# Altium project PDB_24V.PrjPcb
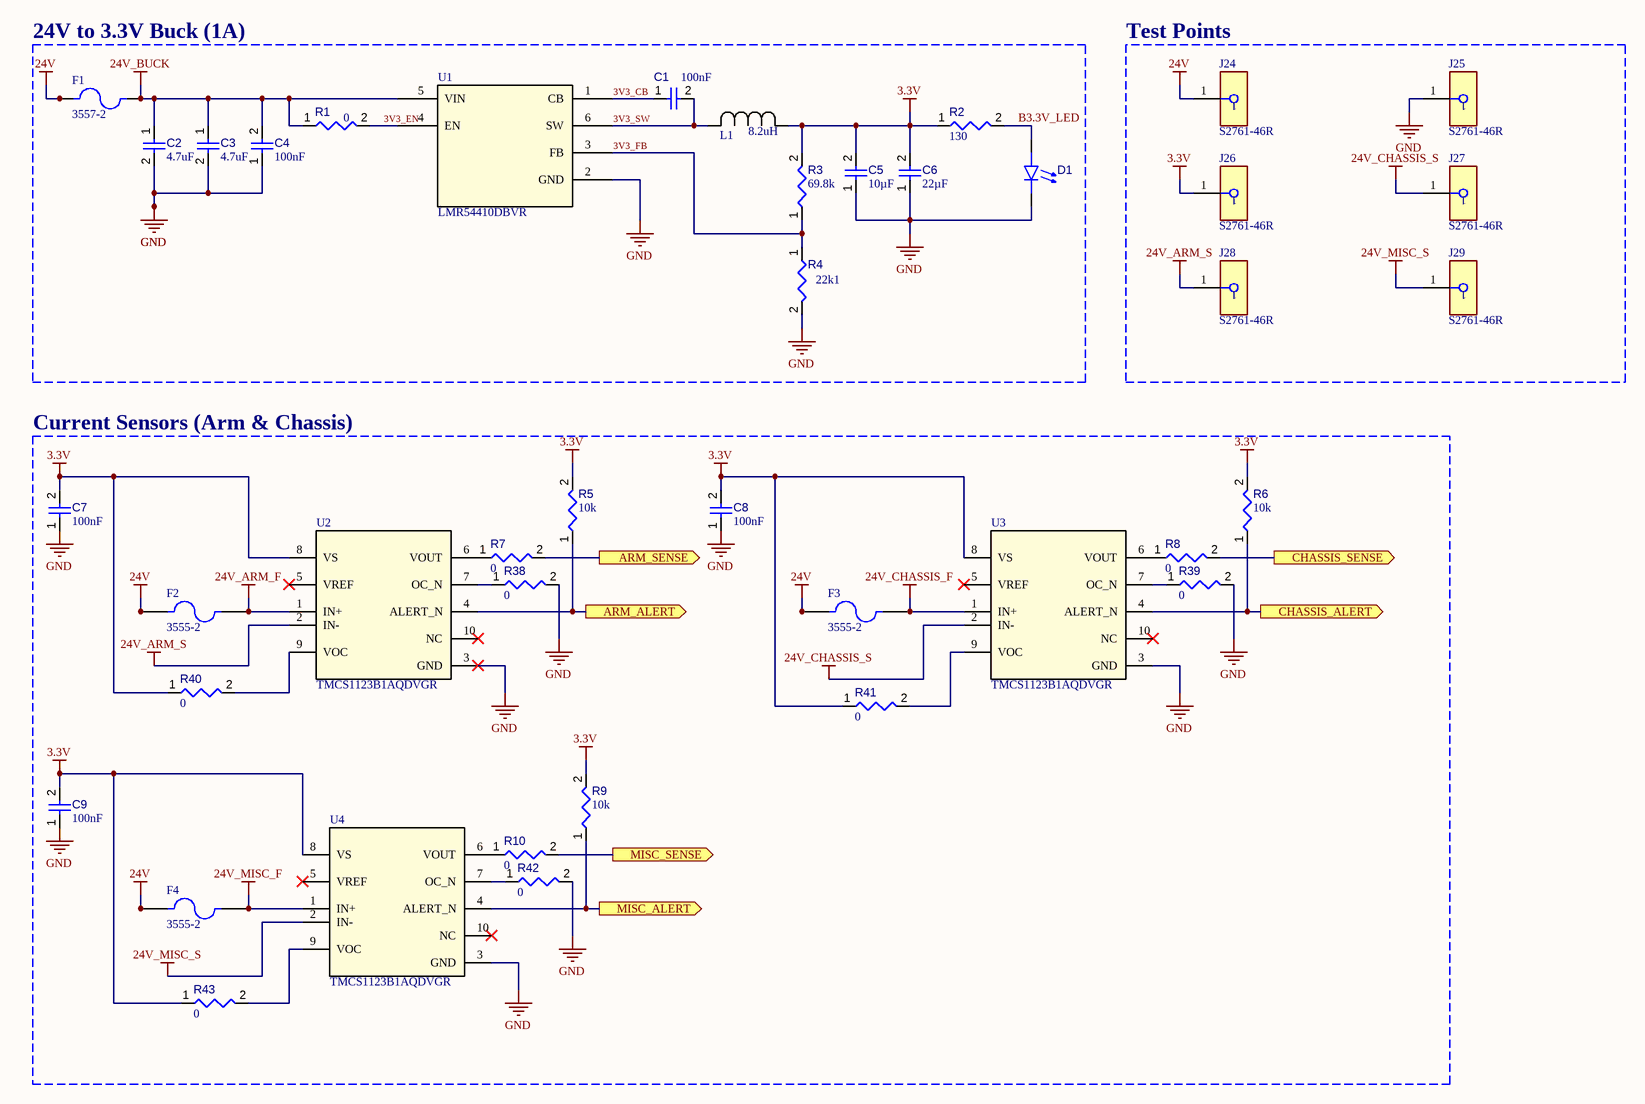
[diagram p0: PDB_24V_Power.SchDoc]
3 sheets, 170 parts. Net scope: flat (ports and power ports of the same name join across sheets).
Board file: PDB_24V.PcbDoc
Sheets:
  PDB_24V_Power.SchDoc
  PDB_24V_Connectors.SchDoc
  PDB_24V_MCU_Peripherals.SchDoc

## Sheet PDB_24V_Power.SchDoc
size A3

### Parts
C1  value 100nF  [FP-CGA3E-0_3-0_1-MFG]  (hidden comment: CGA3E3X8R1H104K080AB)
C2  value 4.7uF  [FP-1210-L_3_3_0_4-W_2_5_0-IPC_A]  (hidden comment: 12105C475KAT2A)
C3  value 4.7uF  [FP-1210-L_3_3_0_4-W_2_5_0-IPC_A]  (hidden comment: 12105C475KAT2A)
C4  value 100nF  [FP-CGA3E-0_3-0_1-MFG]  (hidden comment: CGA3E3X8R1H104K080AB)
C5  value 10µF  [TAYO-C1210-2_M]  (hidden comment: UMK325BJ106MM-T)
C6  value 22µF  [FP-GRM32-MFG]  (hidden comment: GRM32ER61E226KE15L)
C7  value 100nF  [FP-CL830-IPC_C]  (hidden comment: CL05B104KA5NNNC)
C8  value 100nF  [FP-CL830-IPC_C]  (hidden comment: CL05B104KA5NNNC)
C9  value 100nF  [FP-CL830-IPC_C]  (hidden comment: CL05B104KA5NNNC)
D1  150120VS75000  [WL-SMCW_1206_150120xx75000]  (value not drawn)
F1  3557-2  [FUSE_3557-2]
F2  3555-2  [FUSE_3555-2]
F3  3555-2  [FUSE_3555-2]
F4  3555-2  [FUSE_3555-2]
J24  S2761-46R  [FP-S2761-46R-MFG]
J25  S2761-46R  [FP-S2761-46R-MFG]
J26  S2761-46R  [FP-S2761-46R-MFG]
J27  S2761-46R  [FP-S2761-46R-MFG]
J28  S2761-46R  [FP-S2761-46R-MFG]
J29  S2761-46R  [FP-S2761-46R-MFG]
L1  value 8.2uH  [IND_BOURNS_SRN6045]  (hidden comment: SRN6045-8R2Y)
R1  value 0  [FP-RMCF0603-IPC_A]  (hidden comment: RMCF0603ZT0R00)
R2  value 130  [FP-AC0603-MFG]  (hidden comment: AC0603FR-07130RL)
R3  value 69.8k  [FP-CRCW0603-e3-MFG]  (hidden comment: CRCW060369K8FKEB)
R4  value 22k1  [FP-RMCF0603-MFG]  (hidden comment: RMCF0603FT22K1)
R5  value 10k  [FP-RC0603-0_55-MFG]  (hidden comment: RC0603FR-0710KL)
R6  value 10k  [FP-RC0603-0_55-MFG]  (hidden comment: RC0603FR-0710KL)
R7  value 0  [FP-RMCF0603-IPC_A]  (hidden comment: RMCF0603ZT0R00)
R8  value 0  [FP-RMCF0603-IPC_A]  (hidden comment: RMCF0603ZT0R00)
R9  value 10k  [FP-RC0603-0_55-MFG]  (hidden comment: RC0603FR-0710KL)
R10  value 0  [FP-RMCF0603-IPC_A]  (hidden comment: RMCF0603ZT0R00)
R38  value 0  [FP-RMCF0603-IPC_A]  (hidden comment: RMCF0603ZT0R00)
R39  value 0  [FP-RMCF0603-IPC_A]  (hidden comment: RMCF0603ZT0R00)
R40  value 0  [FP-RMCF0603-IPC_A]  (hidden comment: RMCF0603ZT0R00)
R41  value 0  [FP-RMCF0603-IPC_A]  (hidden comment: RMCF0603ZT0R00)
R42  value 0  [FP-RMCF0603-IPC_A]  (hidden comment: RMCF0603ZT0R00)
R43  value 0  [FP-RMCF0603-IPC_A]  (hidden comment: RMCF0603ZT0R00)
U1  LMR54410DBVR  [SOT-23-6-DBV_TEX]
U2  TMCS1123B1AQDVGR  [DVG0010A-MFG]
U3  TMCS1123B1AQDVGR  [DVG0010A-MFG]
U4  TMCS1123B1AQDVGR  [DVG0010A-MFG]

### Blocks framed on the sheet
24V to 3.3V Buck (1A): C1-C6 D1 F1 L1 R1-R4 U1
Test Points: J24-J29
Current Sensors (Arm & Chassis): C7-C9 F2-F4 R5-R10 R38-R43 U2-U4

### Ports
ARM_ALERT (out), ARM_SENSE (out), CHASSIS_ALERT (out), CHASSIS_SENSE (out), MISC_ALERT (out), MISC_SENSE (out)

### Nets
3.3V: C5.2 C6.2 C7.2 C8.2 C9.2 J26.1 L1.1 R2.1 R3.2 R5.2 R6.2 R9.2 R40.1 R41.1 R43.1 U2.8(VS) U3.8(VS) U4.8(VS)
24V: F1.1_1 F1.1_2 F2.1_1 F2.1_2 F3.1_1 F3.1_2 F4.1_1 F4.1_2 J24.1
24V_ARM_F: F2.2_1 F2.2_2 U2.1(IN+)
24V_ARM_S: J28.1 U2.2(IN-)
24V_BUCK: C2.1 C3.1 C4.2 F1.2_1 F1.2_2 R1.1 U1.5(VIN)
24V_CHASSIS_F: F3.2_1 F3.2_2 U3.1(IN+)
24V_CHASSIS_S: J27.1 U3.2(IN-)
24V_MISC_F: F4.2_1 F4.2_2 U4.1(IN+)
24V_MISC_S: J29.1 U4.2(IN-)
GND: C2.2 C3.2 C4.1 C5.1 C6.1 C7.1 C8.1 C9.1 D1.1(K) J25.1 R4.2 R38.2 R39.2 R42.2 U1.2(GND) U2.3(GND) U3.3(GND) U4.3(GND)
3V3_CB: C1.1 U1.1(CB)
3V3_EN: R1.2 U1.4(EN)
3V3_FB: R3.1 R4.1 U1.3(FB)
3V3_SW: C1.2 L1.2 U1.6(SW)
ARM_ALERT: R5.1 U2.4(ALERT_N) ; port ARM_ALERT
ARM_SENSE: R7.2 ; port ARM_SENSE
B3.3V_LED: D1.2(A) R2.2
CHASSIS_ALERT: R6.1 U3.4(ALERT_N) ; port CHASSIS_ALERT
CHASSIS_SENSE: R8.2 ; port CHASSIS_SENSE
MISC_ALERT: R9.1 U4.4(ALERT_N) ; port MISC_ALERT
MISC_SENSE: R10.2 ; port MISC_SENSE
NetR7_1: R7.1 U2.6(VOUT)
NetR8_1: R8.1 U3.6(VOUT)
NetR10_1: R10.1 U4.6(VOUT)
NetR38_1: R38.1 U2.7(OC_N)
NetR39_1: R39.1 U3.7(OC_N)
NetR40_2: R40.2 U2.9(VOC)
NetR41_2: R41.2 U3.9(VOC)
NetR42_1: R42.1 U4.7(OC_N)
NetR43_2: R43.2 U4.9(VOC)

Not connected (* = marked no-connect by the designer): U2 5(VREF)* 10(NC)*; U3 5(VREF)* 10(NC)*; U4 5(VREF)* 10(NC)*

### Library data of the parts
C1 C4 = CMP-001-00163-1: CGA Series 0603 0.1 uF 50 V ±10% Tolerance X8R Multilayer Ceramic Capacitor; Voltage Rating: 50V
C2 C3 = CMP-001-00137-1: Ceramic Capacitor, Multilayer, Ceramic, 50V, 10% +Tol, 10% -Tol, X7R, 15% TC, 4.7uF, Surface Mount, 1210
C5 = CMP-001-00183-1: 50V 10uF X5R ±20% 1210 Multilayer Ceramic Capacitors MLCC - SMD/SMT ROHS
C6 = CMP-001-00168-1: 25V 22uF X5R ±10% 1210 Multilayer Ceramic Capacitors MLCC - SMD/SMT ROHS
C7-C9 = CMP-001-00174-1: 25V 100nF X7R 卤10% 0402 Multilayer Ceramic Capacitors MLCC - SMD/SMT ROHS; Tolerance: 10%
D1 = CMP-007-00044-1: Single Color LED, Bright Green, Water Clear, 2mm; Forward Current: 30mA
F1 = CMP-005-00014-1: THM 2 in 1 Auto Blade Holder; MF: Keystone Electronics
F2-F4 = CMP-005-00015-2: Auto Fuse Holder, 1 Fuse, Blade, Standard, THM, 50Amp, Hi-Temp Nylon, UL94V-0; MF: Keystone Electronics
J24-J29 = CMP-002-00083-1: Interconnection Device
L1 = CMP-006-00036-1: Description; Manufacturer_Name: Bourns Electronics
R1 R7 R8 R10 R38-R43 = CMP-009-00236-1: Fixed Resistor, Metal Glaze/thick Film, 0.1W, 0ohm, Surface Mount, 0603; Power: 100mW
R2 = CMP-009-00292-1: Res Thick Film 0603 130 Ohm 1% 0.1W(1/10W) ±100ppm/C Pad SMD T/R Automotive AEC-Q200; Voltage Rating: 75V
R3 = CMP-009-00297-1: CRCW FIXED RESISTOR 0603 (1608Metric) Chip Resistor ±1% ±100ppm/C 69.8kOhm 0.1W 1/10W; Voltage Rating: 75V
R4 = CMP-009-00240-1: Fixed Resistor, Metal Glaze/thick Film, 0.1W, 22100ohm, 75V, 1% +/-Tol, 100ppm/Cel, Surface Mount, 0603; Power: 100mW
R5 R6 R9 = CMP-009-00288-1: 100mW Thick Film Resistors ±100ppm/℃ ±1% 10kΩ 0603 Chip Resistor - Surface Mount ROHS; Voltage Rating: 75V
U1 = CMP-00030-00008-3: 4V to 36V, 1A, 80-ÂµA Iq synchronous SIMPLE SWITCHERÂ® power converter 6-SOT-23 -40 to 125; Manufacturer_Name: Texas Instruments
U2-U4 = CMP-081-000000-2: Â±1300V reinforced isolation, 80ARMS 250kHz Hall-effect current sensor with AFR, reference and ALERT 10-SOIC -40 to 125; Manufacturer_Name: Texas Instruments

## Sheet PDB_24V_Connectors.SchDoc
size A3
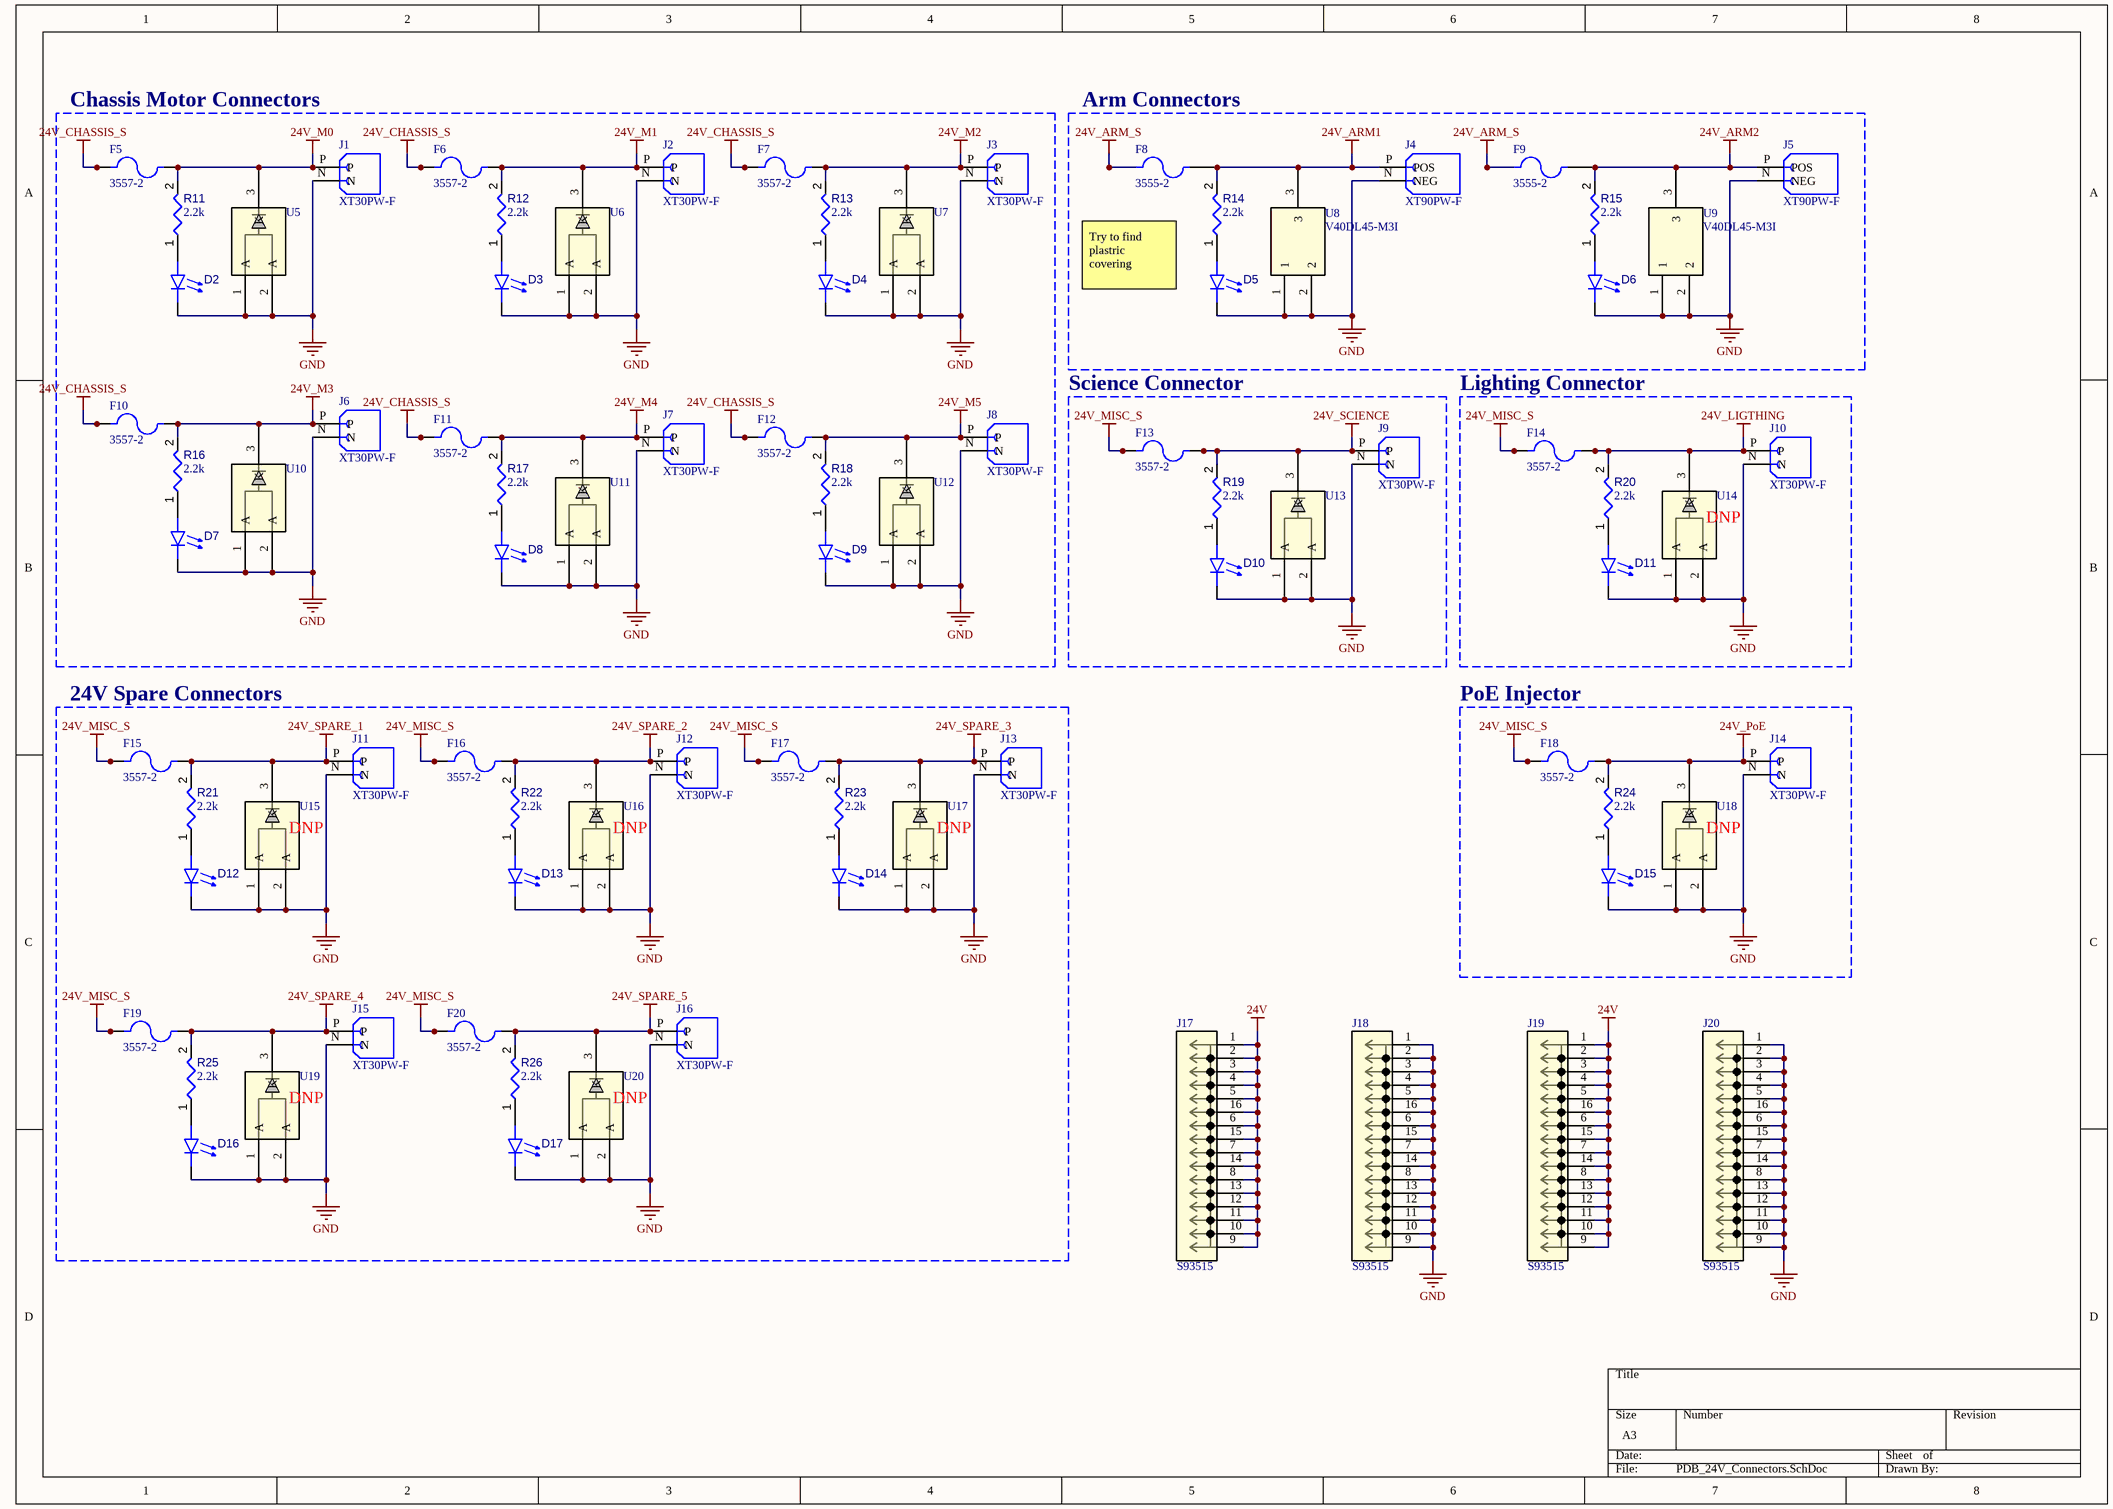
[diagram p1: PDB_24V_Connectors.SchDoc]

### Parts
D2  150120VS75000  [WL-SMCW_1206_150120xx75000]  (value not drawn)
D3  150120VS75000  [WL-SMCW_1206_150120xx75000]  (value not drawn)
D4  150120VS75000  [WL-SMCW_1206_150120xx75000]  (value not drawn)
D5  150120VS75000  [WL-SMCW_1206_150120xx75000]  (value not drawn)
D6  150120VS75000  [WL-SMCW_1206_150120xx75000]  (value not drawn)
D7  150120VS75000  [WL-SMCW_1206_150120xx75000]  (value not drawn)
D8  150120VS75000  [WL-SMCW_1206_150120xx75000]  (value not drawn)
D9  150120VS75000  [WL-SMCW_1206_150120xx75000]  (value not drawn)
D10  150120VS75000  [WL-SMCW_1206_150120xx75000]  (value not drawn)
D11  150120VS75000  [WL-SMCW_1206_150120xx75000]  (value not drawn)
D12  150120VS75000  [WL-SMCW_1206_150120xx75000]  (value not drawn)
D13  150120VS75000  [WL-SMCW_1206_150120xx75000]  (value not drawn)
D14  150120VS75000  [WL-SMCW_1206_150120xx75000]  (value not drawn)
D15  150120VS75000  [WL-SMCW_1206_150120xx75000]  (value not drawn)
D16  150120VS75000  [WL-SMCW_1206_150120xx75000]  (value not drawn)
D17  150120VS75000  [WL-SMCW_1206_150120xx75000]  (value not drawn)
F5  3557-2  [FUSE_3557-2]
F6  3557-2  [FUSE_3557-2]
F7  3557-2  [FUSE_3557-2]
F8  3555-2  [FUSE_3555-2]
F9  3555-2  [FUSE_3555-2]
F10  3557-2  [FUSE_3557-2]
F11  3557-2  [FUSE_3557-2]
F12  3557-2  [FUSE_3557-2]
F13  3557-2  [FUSE_3557-2]
F14  3557-2  [FUSE_3557-2]
F15  3557-2  [FUSE_3557-2]
F16  3557-2  [FUSE_3557-2]
F17  3557-2  [FUSE_3557-2]
F18  3557-2  [FUSE_3557-2]
F19  3557-2  [FUSE_3557-2]
F20  3557-2  [FUSE_3557-2]
J1  XT30PW-F  [AMASS_XT30PW-F]
J2  XT30PW-F  [AMASS_XT30PW-F]
J3  XT30PW-F  [AMASS_XT30PW-F]
J4  XT90PW-F  [AMASS_XT90PW-F]
J5  XT90PW-F  [AMASS_XT90PW-F]
J6  XT30PW-F  [AMASS_XT30PW-F]
J7  XT30PW-F  [AMASS_XT30PW-F]
J8  XT30PW-F  [AMASS_XT30PW-F]
J9  XT30PW-F  [AMASS_XT30PW-F]
J10  XT30PW-F  [AMASS_XT30PW-F]
J11  XT30PW-F  [AMASS_XT30PW-F]
J12  XT30PW-F  [AMASS_XT30PW-F]
J13  XT30PW-F  [AMASS_XT30PW-F]
J14  XT30PW-F  [AMASS_XT30PW-F]
J15  XT30PW-F  [AMASS_XT30PW-F]
J16  XT30PW-F  [AMASS_XT30PW-F]
J17  S93515  [CONN16_S93515_WRE]
J18  S93515  [CONN16_S93515_WRE]
J19  S93515  [CONN16_S93515_WRE]
J20  S93515  [CONN16_S93515_WRE]
R11  value 2.2k  [RESC1608X55X25LL10T15]  (hidden comment: RC0603FR-072K2L)
R12  value 2.2k  [RESC1608X55X25LL10T15]  (hidden comment: RC0603FR-072K2L)
R13  value 2.2k  [RESC1608X55X25LL10T15]  (hidden comment: RC0603FR-072K2L)
R14  value 2.2k  [RESC1608X55X25LL10T15]  (hidden comment: RC0603FR-072K2L)
R15  value 2.2k  [RESC1608X55X25LL10T15]  (hidden comment: RC0603FR-072K2L)
R16  value 2.2k  [RESC1608X55X25LL10T15]  (hidden comment: RC0603FR-072K2L)
R17  value 2.2k  [RESC1608X55X25LL10T15]  (hidden comment: RC0603FR-072K2L)
R18  value 2.2k  [RESC1608X55X25LL10T15]  (hidden comment: RC0603FR-072K2L)
R19  value 2.2k  [RESC1608X55X25LL10T15]  (hidden comment: RC0603FR-072K2L)
R20  value 2.2k  [RESC1608X55X25LL10T15]  (hidden comment: RC0603FR-072K2L)
R21  value 2.2k  [RESC1608X55X25LL10T15]  (hidden comment: RC0603FR-072K2L)
R22  value 2.2k  [RESC1608X55X25LL10T15]  (hidden comment: RC0603FR-072K2L)
R23  value 2.2k  [RESC1608X55X25LL10T15]  (hidden comment: RC0603FR-072K2L)
R24  value 2.2k  [RESC1608X55X25LL10T15]  (hidden comment: RC0603FR-072K2L)
R25  value 2.2k  [RESC1608X55X25LL10T15]  (hidden comment: RC0603FR-072K2L)
R26  value 2.2k  [RESC1608X55X25LL10T15]  (hidden comment: RC0603FR-072K2L)
U5  SDT30B100D1-13  [TO252_DIO]  (value not drawn)
U6  SDT30B100D1-13  [TO252_DIO]  (value not drawn)
U7  SDT30B100D1-13  [TO252_DIO]  (value not drawn)
U8  V40DL45-M3I  [SOT_45-M3I_VIS]
U9  V40DL45-M3I  [SOT_45-M3I_VIS]
U10  SDT30B100D1-13  [TO252_DIO]  (value not drawn)
U11  SDT30B100D1-13  [TO252_DIO]  (value not drawn)
U12  SDT30B100D1-13  [TO252_DIO]  (value not drawn)
U13  SDT30B100D1-13  [TO252_DIO]  (value not drawn)
U14  SDT30B100D1-13  [TO252_DIO]  (value not drawn)
U15  SDT30B100D1-13  [TO252_DIO]  (value not drawn)
U16  SDT30B100D1-13  [TO252_DIO]  (value not drawn)
U17  SDT30B100D1-13  [TO252_DIO]  (value not drawn)
U18  SDT30B100D1-13  [TO252_DIO]  (value not drawn)
U19  SDT30B100D1-13  [TO252_DIO]  (value not drawn)
U20  SDT30B100D1-13  [TO252_DIO]  (value not drawn)

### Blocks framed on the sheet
Chassis Motor Connectors: D2-D4 D7-D9 F5-F7 F10-F12 J1-J3 J6-J8 R11-R13 R16-R18 U5-U7 U10-U12
Arm Connectors: D5 D6 F8 F9 J4 J5 R14 R15 U8 U9
Science Connector: D10 F13 J9 R19 U13
Lighting Connector: D11 F14 J10 R20 U14
24V Spare Connectors: D12-D14 D16 D17 F15-F17 F19 F20 J11-J13 J15 J16 R21-R23 R25 R26 U15-U17 U19 U20
PoE Injector: D15 F18 J14 R24 U18

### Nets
24V: J17.1 J17.2 J17.3 J17.4 J17.5 J17.6 J17.7 J17.8 J17.9 J17.10 J17.11 J17.12 J17.13 J17.14 J17.15 J17.16 J19.1 J19.2 J19.3 J19.4 J19.5 J19.6 J19.7 J19.8 J19.9 J19.10 J19.11 J19.12 J19.13 J19.14 J19.15 J19.16
24V_ARM1: F8.2_1 F8.2_2 J4.P(POS) R14.2 U8.3
24V_ARM2: F9.2_1 F9.2_2 J5.P(POS) R15.2 U9.3
24V_ARM_S: F8.1_1 F8.1_2 F9.1_1 F9.1_2
24V_CHASSIS_S: F5.1_1 F5.1_2 F6.1_1 F6.1_2 F7.1_1 F7.1_2 F10.1_1 F10.1_2 F11.1_1 F11.1_2 F12.1_1 F12.1_2
24V_LIGTHING: F14.2_1 F14.2_2 J10.P R20.2 U14.3(K)
24V_M0: F5.2_1 F5.2_2 J1.P R11.2 U5.3(K)
24V_M1: F6.2_1 F6.2_2 J2.P R12.2 U6.3(K)
24V_M2: F7.2_1 F7.2_2 J3.P R13.2 U7.3(K)
24V_M3: F10.2_1 F10.2_2 J6.P R16.2 U10.3(K)
24V_M4: F11.2_1 F11.2_2 J7.P R17.2 U11.3(K)
24V_M5: F12.2_1 F12.2_2 J8.P R18.2 U12.3(K)
24V_MISC_S: F13.1_1 F13.1_2 F14.1_1 F14.1_2 F15.1_1 F15.1_2 F16.1_1 F16.1_2 F17.1_1 F17.1_2 F18.1_1 F18.1_2 F19.1_1 F19.1_2 F20.1_1 F20.1_2
24V_PoE: F18.2_1 F18.2_2 J14.P R24.2 U18.3(K)
24V_SCIENCE: F13.2_1 F13.2_2 J9.P R19.2 U13.3(K)
24V_SPARE_1: F15.2_1 F15.2_2 J11.P R21.2 U15.3(K)
24V_SPARE_2: F16.2_1 F16.2_2 J12.P R22.2 U16.3(K)
24V_SPARE_3: F17.2_1 F17.2_2 J13.P R23.2 U17.3(K)
24V_SPARE_4: F19.2_1 F19.2_2 J15.P R25.2 U19.3(K)
24V_SPARE_5: F20.2_1 F20.2_2 J16.P R26.2 U20.3(K)
GND: D2.1(K) D3.1(K) D4.1(K) D5.1(K) D6.1(K) D7.1(K) D8.1(K) D9.1(K) D10.1(K) D11.1(K) D12.1(K) D13.1(K) D14.1(K) D15.1(K) D16.1(K) D17.1(K) J1.N J2.N J3.N J4.N(NEG) J5.N(NEG) J6.N J7.N J8.N J9.N J10.N J11.N J12.N J13.N J14.N J15.N J16.N J18.1 J18.2 J18.3 J18.4 J18.5 J18.6 J18.7 J18.8 J18.9 J18.10 J18.11 J18.12 J18.13 J18.14 J18.15 J18.16 J20.1 J20.2 J20.3 J20.4 J20.5 J20.6 J20.7 J20.8 J20.9 J20.10 J20.11 J20.12 J20.13 J20.14 J20.15 J20.16 U5.1(A) U5.2(A) U6.1(A) U6.2(A) U7.1(A) U7.2(A) U8.1 U8.2 U9.1 U9.2 U10.1(A) U10.2(A) U11.1(A) U11.2(A) U12.1(A) U12.2(A) U13.1(A) U13.2(A) U14.1(A) U14.2(A) U15.1(A) U15.2(A) U16.1(A) U16.2(A) U17.1(A) U17.2(A) U18.1(A) U18.2(A) U19.1(A) U19.2(A) U20.1(A) U20.2(A)
NetD2_2: D2.2(A) R11.1
NetD3_2: D3.2(A) R12.1
NetD4_2: D4.2(A) R13.1
NetD5_2: D5.2(A) R14.1
NetD6_2: D6.2(A) R15.1
NetD7_2: D7.2(A) R16.1
NetD8_2: D8.2(A) R17.1
NetD9_2: D9.2(A) R18.1
NetD10_2: D10.2(A) R19.1
NetD11_2: D11.2(A) R20.1
NetD12_2: D12.2(A) R21.1
NetD13_2: D13.2(A) R22.1
NetD14_2: D14.2(A) R23.1
NetD15_2: D15.2(A) R24.1
NetD16_2: D16.2(A) R25.1
NetD17_2: D17.2(A) R26.1

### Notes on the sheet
- Try to find plastric covering
- (near U14) DNP
- (near U15) DNP
- (near U16) DNP
- (near U17) DNP
- (near U18) DNP
- (near U19) DNP
- (near U20) DNP

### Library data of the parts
D2-D17 = CMP-007-00044-1: as D1 on sheet PDB_24V_Power
F5-F7 F10-F20 = CMP-005-00014-1: as F1 on sheet PDB_24V_Power
F8 F9 = CMP-005-00015-2: as F2 on sheet PDB_24V_Power
J1-J3 J6-J16 = CMP-002-00091-1: Socket; DC supply; XT30; female; PIN: 2; on PCBs; THT; yellow; 15A; MF: amass
J4 J5 = CMP-002-00096-1: Socket, DC supply, XT90, female, PIN:2, on PCBs, THT; MF: AMASS
J17-J20 = CMP-083-000000-2: Description; Manufacturer_Name: Wurth Electronics
R11-R26 = CMP-009-00296-1: 100Mw Thick Film Resistors 100Ppm/ 1% 2.2K 0603 Chip Resistor Surface Mount Rohs; Voltage Rating: 75V
U5-U7 U10-U20 = CMP-004-00037-2: Description; Manufacturer_Name: Diodes Inc
U8 U9 = CMP-079-000001-3: 40A, 45V,TRENCH SKY RECT.; Manufacturer_Part_Number: V40DL45-M3/I; Manufacturer_Name: Vishay

## Sheet PDB_24V_MCU_Peripherals.SchDoc
size A3
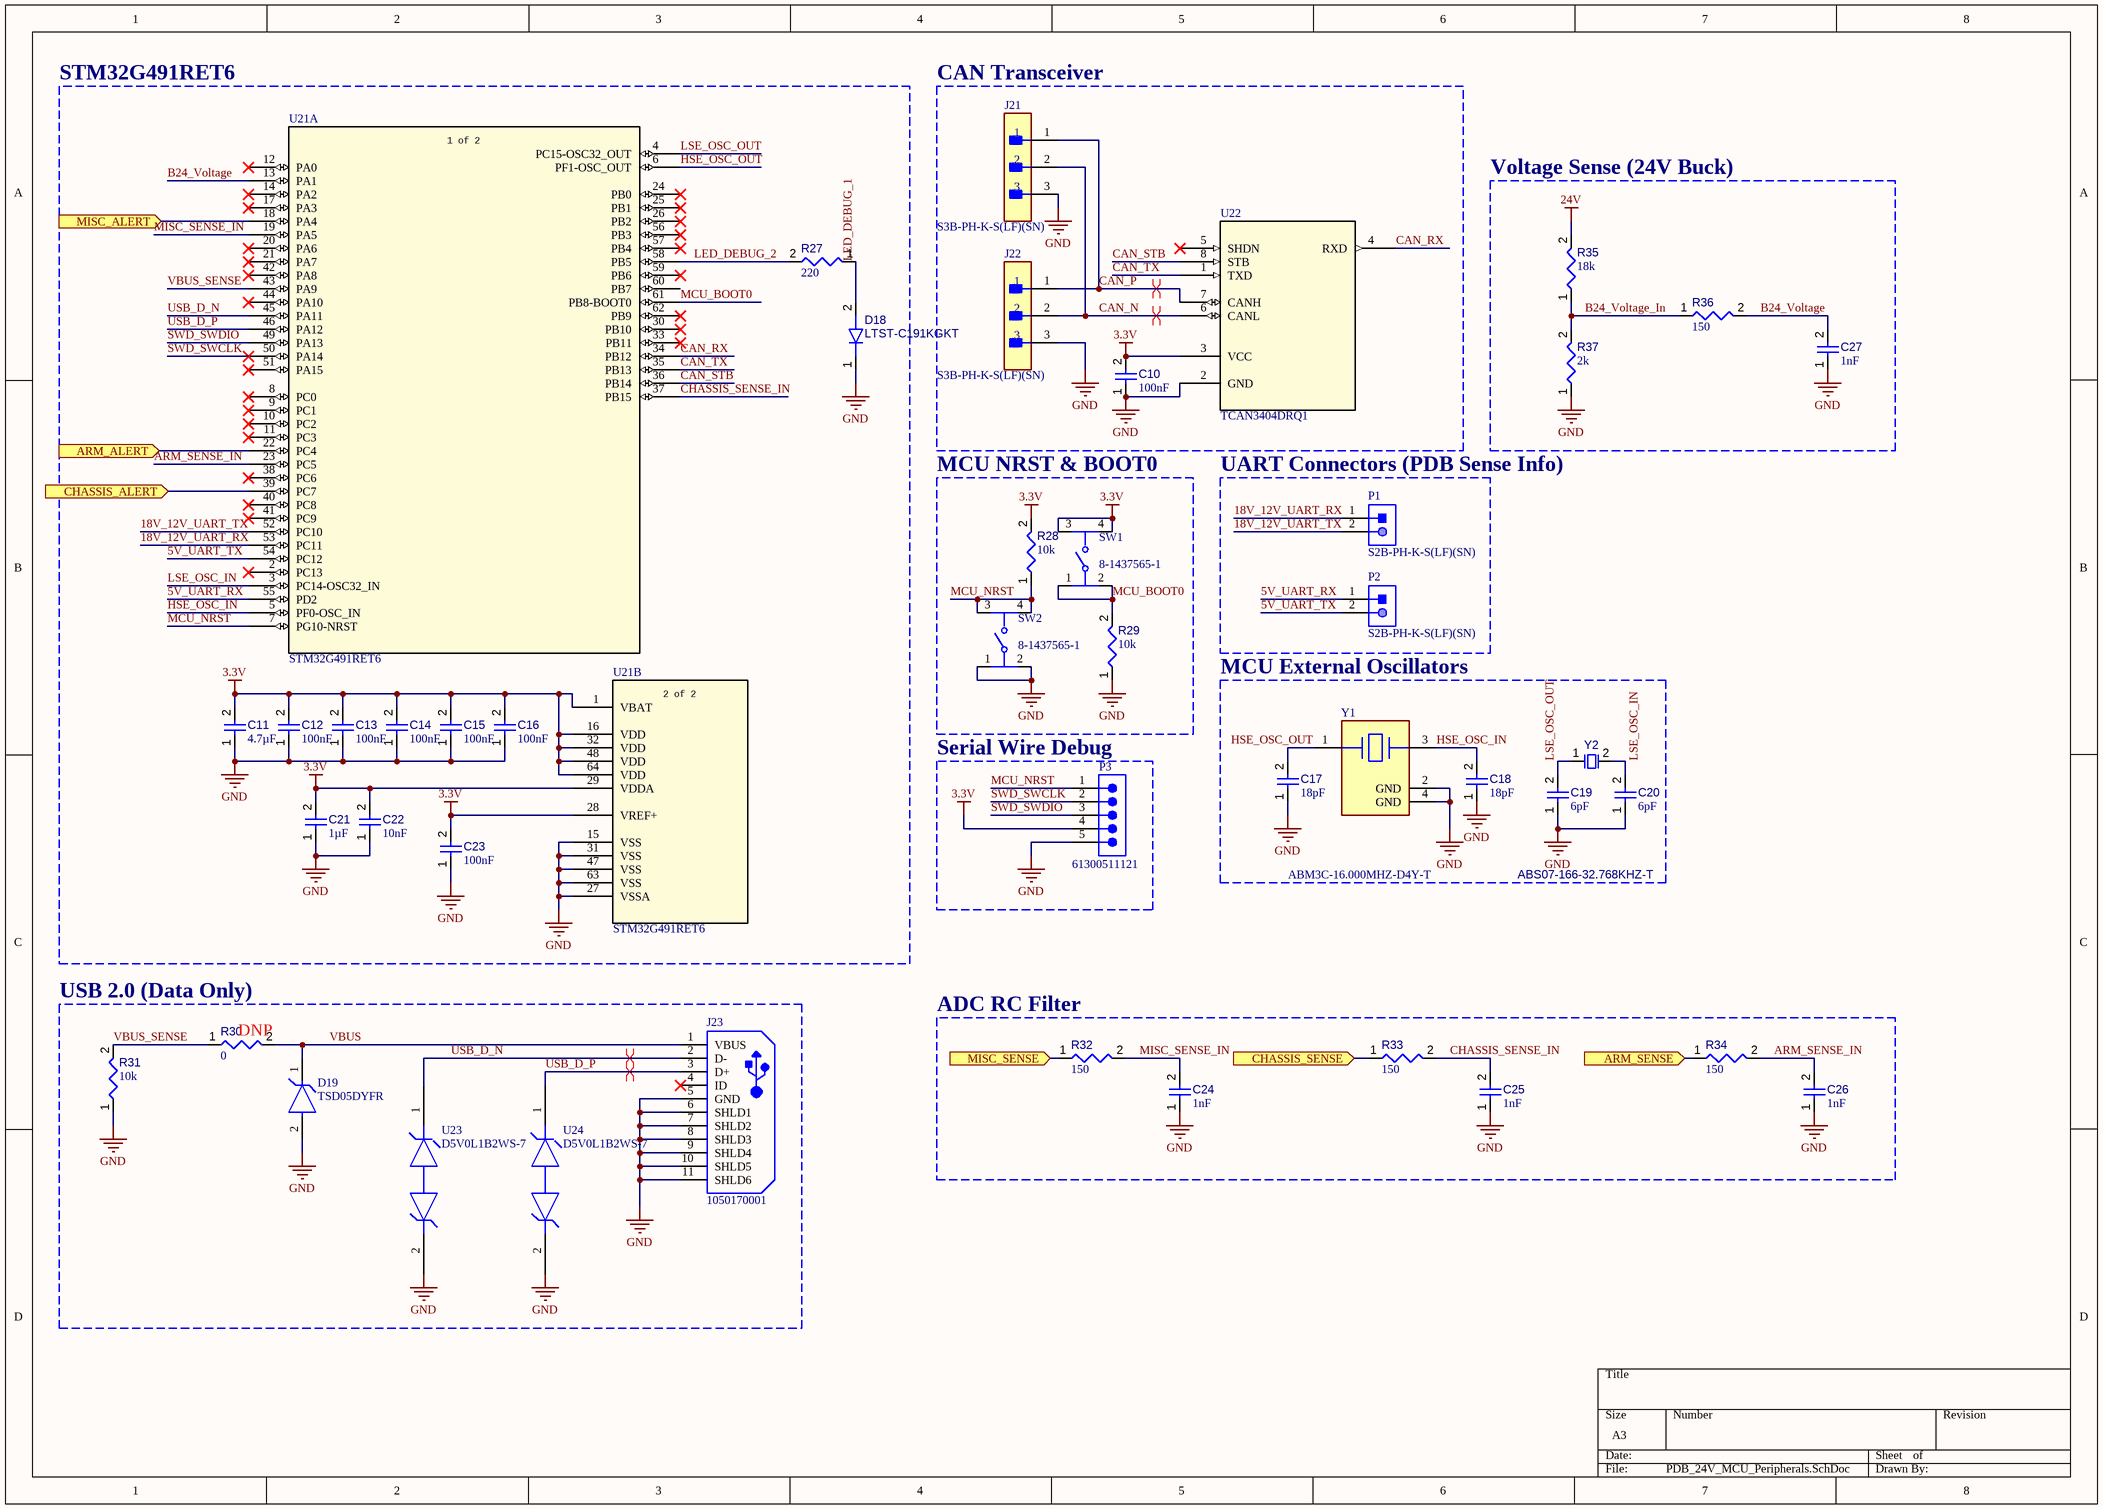
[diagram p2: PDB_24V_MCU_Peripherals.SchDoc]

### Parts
C10  value 100nF  [FP-CL830-IPC_C]  (hidden comment: CL05B104KA5NNNC)
C11  value 4.7µF  [FP-GRM188-0_15-MFG]  (hidden comment: GRM188R61E475KE11D)
C12  value 100nF  [FP-CL830-IPC_C]  (hidden comment: CL05B104KA5NNNC)
C13  value 100nF  [FP-CL830-IPC_C]  (hidden comment: CL05B104KA5NNNC)
C14  value 100nF  [FP-CL830-IPC_C]  (hidden comment: CL05B104KA5NNNC)
C15  value 100nF  [FP-CL830-IPC_C]  (hidden comment: CL05B104KA5NNNC)
C16  value 100nF  [FP-CL830-IPC_C]  (hidden comment: CL05B104KA5NNNC)
C17  value 18pF  [CAPC1005X55X25LL05T10]  (hidden comment: GRM1555C1H180JA01D)
C18  value 18pF  [CAPC1005X55X25LL05T10]  (hidden comment: GRM1555C1H180JA01D)
C19  value 6pF  [FP-CL10-IPC_C]  (hidden comment: CL10C060DB8NNNC)
C20  value 6pF  [FP-CL10-IPC_C]  (hidden comment: CL10C060DB8NNNC)
C21  value 1µF  [FP-CC0603-DA-MFG]  (hidden comment: CC0603KRX7R7BB105)
C22  value 10nF  [CAPC1608X90X35LL10T15]  (hidden comment: GCM188R71H103KA37D)
C23  value 100nF  [FP-CL830-IPC_C]  (hidden comment: CL05B104KA5NNNC)
C24  value 1nF  [FP-GRM155-0_05-MFG]  (hidden comment: GRM1555C1H102JA01D)
C25  value 1nF  [FP-GRM155-0_05-MFG]  (hidden comment: GRM1555C1H102JA01D)
C26  value 1nF  [FP-GRM155-0_05-MFG]  (hidden comment: GRM1555C1H102JA01D)
C27  value 1nF  [FP-GRM155-0_05-MFG]  (hidden comment: GRM1555C1H102JA01D)
D18  LTST-C191KGKT  [FP-LTST-C191KGKT-MFG]
D19  TSD05DYFR  [FP-DYF0002A-MFG]
J21  S3B-PH-K-S(LF)(SN)  [FP-S3B-PH-K-S_LF_SN-MFG]
J22  S3B-PH-K-S(LF)(SN)  [FP-S3B-PH-K-S_LF_SN-MFG]
J23  1050170001  [USB-MICRO-B_V]
P1  S2B-PH-K-S(LF)(SN)  [JST-S2B-PH-K-S_V]
P2  S2B-PH-K-S(LF)(SN)  [JST-S2B-PH-K-S_V]
P3  61300511121  [61300511121]
R27  value 220  [FP-CRGCQ0603-IPC_C]  (hidden comment: CRGCQ0603J220R)
R28  value 10k  [FP-RC0603-0_55-MFG]  (hidden comment: RC0603FR-0710KL)
R29  value 10k  [FP-RC0603-0_55-MFG]  (hidden comment: RC0603FR-0710KL)
R30  value 0  [FP-RMCF0603-IPC_A]  (hidden comment: RMCF0603ZT0R00)
R31  value 10k  [FP-RC0603-0_55-MFG]  (hidden comment: RC0603FR-0710KL)
R32  value 150  [RESC1005X40X25LL05T10]  (hidden comment: RC0402FR-07150RL)
R33  value 150  [RESC1005X40X25LL05T10]  (hidden comment: RC0402FR-07150RL)
R34  value 150  [RESC1005X40X25LL05T10]  (hidden comment: RC0402FR-07150RL)
R35  value 18k  [FP-AC0603-MFG]  (hidden comment: AC0603FR-0718KL)
R36  value 150  [RESC1005X40X25LL05T10]  (hidden comment: RC0402FR-07150RL)
R37  value 2k  [RESC1608X55X30LL15T15]  (hidden comment: ERJ-3EKF2001V)
SW1  8-1437565-1  [FP-8-1437565-1-MFG]
SW2  8-1437565-1  [FP-8-1437565-1-MFG]
U21  STM32G491RET6  [LQFP64_10X10_STM]  (parts A,B of 2)
U22  TCAN3404DRQ1  [SOIC8_D_TEX]
U23  D5V0L1B2WS-7  [SOD323_DIO]
U24  D5V0L1B2WS-7  [SOD323_DIO]
Y1  ABM3C-16.000MHZ-D4Y-T  [FP-ABM3C-MFG]
Y2  ABS07-166-32.768KHZ-T  [EPSON-FC-135_V]

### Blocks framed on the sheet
STM32G491RET6: C11-C16 C21-C23 D18 R27 U21
CAN Transceiver: C10 J21 J22 U22
Voltage Sense (24V Buck): C27 R35-R37
MCU NRST & BOOT0: R28 R29 SW1 SW2
UART Connectors (PDB Sense Info): P1 P2
MCU External Oscillators: C17-C20 Y1 Y2
Serial Wire Debug: P3
USB 2.0 (Data Only): D19 J23 R30 R31 U23 U24
ADC RC Filter: C24-C26 R32-R34

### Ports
ARM_ALERT (in), ARM_SENSE (in), CHASSIS_ALERT (in), CHASSIS_SENSE (in), MISC_ALERT (in), MISC_SENSE (in)

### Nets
3.3V: C10.2 C11.2 C12.2 C13.2 C14.2 C15.2 C16.2 C21.2 C22.2 C23.2 P3.4 R28.2 SW1.3 SW1.4 U21.1(VBAT) U21.16(VDD) U21.28(VREF+) U21.29(VDDA) U21.32(VDD) U21.48(VDD) U21.64(VDD) U22.3(VCC)
24V: R35.2
GND: C10.1 C11.1 C12.1 C13.1 C14.1 C15.1 C16.1 C17.1 C18.1 C19.1 C20.1 C21.1 C22.1 C23.1 C24.1 C25.1 C26.1 C27.1 D18.1(K) D19.2(GND) J21.3 J22.3 J23.5(GND) J23.6(SHLD1) J23.7(SHLD2) J23.8(SHLD3) J23.9(SHLD4) J23.10(SHLD5) J23.11(SHLD6) P3.5 R29.1 R31.1 R37.1 SW2.1 SW2.2 U21.15(VSS) U21.27(VSSA) U21.31(VSS) U21.47(VSS) U21.63(VSS) U22.2(GND) U23.2(EPAD) U24.2(EPAD) Y1.2(GND) Y1.4(GND)
5V_UART_RX: P2.1 U21.55(PD2)
5V_UART_TX: P2.2 U21.54(PC12)
18V_12V_UART_RX: P1.1 U21.53(PC11)
18V_12V_UART_TX: P1.2 U21.52(PC10)
ARM_ALERT: U21.22(PC4) ; port ARM_ALERT
ARM_SENSE: R34.1 ; port ARM_SENSE
ARM_SENSE_IN: C26.2 R34.2 U21.23(PC5)
B24_Voltage: C27.2 R36.2 U21.13(PA1)
B24_Voltage_In: R35.1 R36.1 R37.2
CAN_N: J21.2 J22.2 U22.6(CANL)
CAN_P: J21.1 J22.1 U22.7(CANH)
CAN_RX: U21.34(PB12) U22.4(RXD)
CAN_STB: U21.36(PB14) U22.8(STB)
CAN_TX: U21.35(PB13) U22.1(TXD)
CHASSIS_ALERT: U21.39(PC7) ; port CHASSIS_ALERT
CHASSIS_SENSE: R33.1 ; port CHASSIS_SENSE
CHASSIS_SENSE_IN: C25.2 R33.2 U21.37(PB15)
HSE_OSC_IN: C18.2 U21.5(PF0-OSC_IN) Y1.3
HSE_OSC_OUT: C17.2 U21.6(PF1-OSC_OUT) Y1.1
LED_DEBUG_1: D18.2(A) R27.1
LED_DEBUG_2: R27.2 U21.58(PB5)
LSE_OSC_IN: C20.2 U21.3(PC14-OSC32_IN) Y2.2
LSE_OSC_OUT: C19.2 U21.4(PC15-OSC32_OUT) Y2.1
MCU_BOOT0: R29.2 SW1.1 SW1.2 U21.61(PB8-BOOT0)
MCU_NRST: P3.1 R28.1 SW2.3 SW2.4 U21.7(PG10-NRST)
MISC_ALERT: U21.18(PA4) ; port MISC_ALERT
MISC_SENSE: R32.1 ; port MISC_SENSE
MISC_SENSE_IN: C24.2 R32.2 U21.19(PA5)
SWD_SWCLK: P3.2 U21.50(PA14)
SWD_SWDIO: P3.3 U21.49(PA13)
USB_D_N: J23.2(D-) U21.45(PA11) U23.1(EPAD)
USB_D_P: J23.3(D+) U21.46(PA12) U24.1(EPAD)
VBUS: D19.1(IO) J23.1(VBUS) R30.2
VBUS_SENSE: R30.1 R31.2 U21.43(PA9)

Not connected (* = marked no-connect by the designer): J23 4(ID)*; U21 2(PC13)* 8(PC0)* 9(PC1)* 10(PC2)* 11(PC3)* 12(PA0)* 14(PA2)* 17(PA3)* 20(PA6)* 21(PA7)* 24(PB0)* 25(PB1)* 26(PB2)* 30(PB10)* 33(PB11)* 38(PC6)* 40(PC8)* 41(PC9)* 42(PA8)* 44(PA10)* 51(PA15)* 56(PB3)* 57(PB4)* 59(PB6)* 60(PB7) 62(PB9)*; U22 5(SHDN)*

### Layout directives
differential pair: CAN_N, CAN_P, USB_D_N
differential pair; net class USB: USB_D_P

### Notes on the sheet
- (near R30) DNP

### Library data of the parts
C10 C12-C16 C23 = CMP-001-00174-1: as C7 on sheet PDB_24V_Power
C11 = CMP-001-00175-1: 25V 4.7uF X5R ±10% 0603 Multilayer Ceramic Capacitors MLCC - SMD/SMT ROHS
C17 C18 = CMP-001-00180-1: 50V 18pF C0G ±5% 0402 Multilayer Ceramic Capacitors MLCC - SMD/SMT ROHS
C19 C20 = CMP-001-00181-1: 50V 6pF C0G 0603 Multilayer Ceramic Capacitors MLCC - SMD/SMT ROHS
C21 = CMP-001-00172-1: 16V 1uF X7R ±10% 0603 Multilayer Ceramic Capacitors MLCC - SMD/SMT ROHS
C22 = CMP-001-00176-1: 50V 10nF X7R ±10% 0603 Multilayer Ceramic Capacitors MLCC - SMD/SMT ROHS
C24-C27 = CMP-001-00142-1: Ceramic Capacitor, Multilayer, Ceramic, 50V, 5% +Tol, 5% -Tol, C0G, 30ppm/Cel TC, 0.001uF, Surface Mount, 0402
D18 = CMP-004-00036-1: LED yellow green 0603 wavelength 567.5~576.5nm light intensity 18~71mcd Front Mounting; Forward Voltage: 2.4V; Forward Current: 30mA
D19 = CMP-004-00040-1: 5-V 60-A Unidirectional surge protection device 2-SOT -40 to 125
J21 J22 = CMP-002-00094-1: Board Connector, 3 Contact(s), 1 Row(s), Male, Right Angle, Solder Terminal; Voltage Rating: 100V; Max Current Rating: 2A; Connector Type: Male Pin
J23 = CMP-002-00081-1: Telecom and Datacom Connector, 5 Contact(s), Female, Right Angle, Surface Mount Terminal, Detent, Receptacle
P1 P2 = CMP-002-00030-2: Male Header, Pitch 2 mm, 1 x 2 Position, Height 4.8 mm, Tail Length 3.4 mm, -25 to 85 degC, RoHS, Bulk; Manufacturer: Japan Solderless Terminals
P3 = CMP-002-00093-1: WR-PHD Straight Male, PCB Header, Through Hole, 1 Rows, 5 Contacts, 2.54mm Pitch; Connector Type: Male Pin; Voltage Rating: 250V
R27 = CMP-009-00289-1: Res Thick Film 0603 220 Ohm 5% 0.1W(1/10W) ±100ppm/C Pad SMD Automotive T/R; Voltage Rating: 75V
R28 R29 R31 = CMP-009-00288-1: as R5 on sheet PDB_24V_Power
R30 = CMP-009-00236-1: as R1 on sheet PDB_24V_Power
R32-R34 R36 = CMP-009-00298-1: Yageo RC0402FR-07150RL Resistor 0603 SMD 150 Ohm precision thick film; Voltage Rating: 50V; Tolerance: 1%
R35 = CMP-009-00299-1: Res Thick Film 0603 18K Ohm 1% 0.1W(1/10W) ±100ppm/C Pad SMD T/R Automotive AEC-Q200; Voltage Rating: 75V
R37 = CMP-009-00293-1: Res Thick Film 0603 2K Ohm 1% 1/10W ±100ppm/°C Molded SMD Punched Carrier T/R; Voltage Rating: 75V
SW1 SW2 = CMP-011-00018-1: Switch Tactile OFF (ON) SPST Round Button Gull Wing 0.05A 24VDC 2.55N SMD T/R; Max Current Rating: 20mA
U21 = CMP-031-00007-1: Mainstream Arm Cortex-M4 MCU 170 MHz with 512 Kbytes of Flash memory, Math Accelerator, High Analog level integration; Manufacturer_Name: STMicroelectronics
U22 = CMP-064-000000-2: Automotive 3.3V CAN flexible-data-rate (FD) transceiver with shutdown and standby mode 8-SOIC -40 to 150; Manufacturer_Name: Texas Instruments
U23 U24 = CMP-093-000000-4: Description; Manufacturer_Name: Diodes Inc
Y1 = CMP-003-00033-1: Crystal, Standard, 16 MHz, SMD, 5mm x 3.2mm x 1.3mm, 30 ppm, 18 pF, 30 ppm, ABM3C; Load Capacitance: 18pF; ESR: 50; Frequency: 16MHz
Y2 = CMP-003-00029-1: Crystal 32.768kHz 10ppm 7pF -40C +85C

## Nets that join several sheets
3.3V: PDB_24V_Power (18 pins), PDB_24V_MCU_Peripherals (22 pins)
24V: PDB_24V_Power (9 pins), PDB_24V_Connectors (32 pins), PDB_24V_MCU_Peripherals (R35.2)
24V_ARM_S: PDB_24V_Power (J28.1 U2.2), PDB_24V_Connectors (F8.1_1 F8.1_2 F9.1_1 F9.1_2)
24V_CHASSIS_S: PDB_24V_Power (J27.1 U3.2), PDB_24V_Connectors (12 pins)
24V_MISC_S: PDB_24V_Power (J29.1 U4.2), PDB_24V_Connectors (16 pins)
GND: PDB_24V_Power (18 pins), PDB_24V_Connectors (96 pins), PDB_24V_MCU_Peripherals (45 pins)
ARM_ALERT: PDB_24V_Power (R5.1 U2.4), PDB_24V_MCU_Peripherals (U21.22)
ARM_SENSE: PDB_24V_Power (R7.2), PDB_24V_MCU_Peripherals (R34.1)
CHASSIS_ALERT: PDB_24V_Power (R6.1 U3.4), PDB_24V_MCU_Peripherals (U21.39)
CHASSIS_SENSE: PDB_24V_Power (R8.2), PDB_24V_MCU_Peripherals (R33.1)
MISC_ALERT: PDB_24V_Power (R9.1 U4.4), PDB_24V_MCU_Peripherals (U21.18)
MISC_SENSE: PDB_24V_Power (R10.2), PDB_24V_MCU_Peripherals (R32.1)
